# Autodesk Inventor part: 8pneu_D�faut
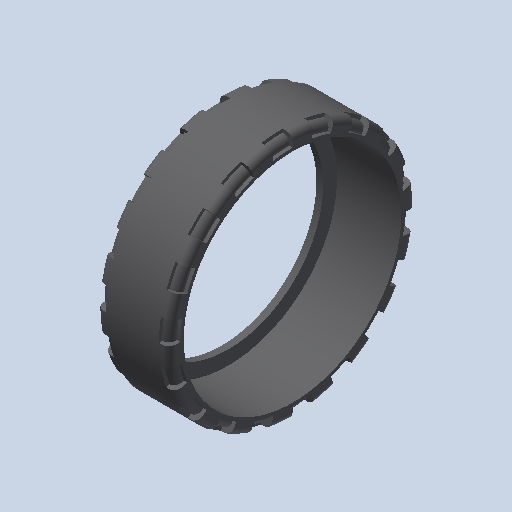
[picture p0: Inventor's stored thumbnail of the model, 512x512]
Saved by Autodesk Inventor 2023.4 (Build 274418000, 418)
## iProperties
Created: 2011-01
Part Number: 8pneu_D�faut
Document SubType Name: Modeling
Designer: eric
Density: 1 g/cm^3
Mass: 179.885 g
Surface Area: 527.045 cm^2
Volume: 179.885 cm^3
Material: Générique
Appearance: 128,128,128_1
Author: eric
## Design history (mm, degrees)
feature "Base1"
node "Corps solides"
node "Corps surfaciques"
node "Solide1"
